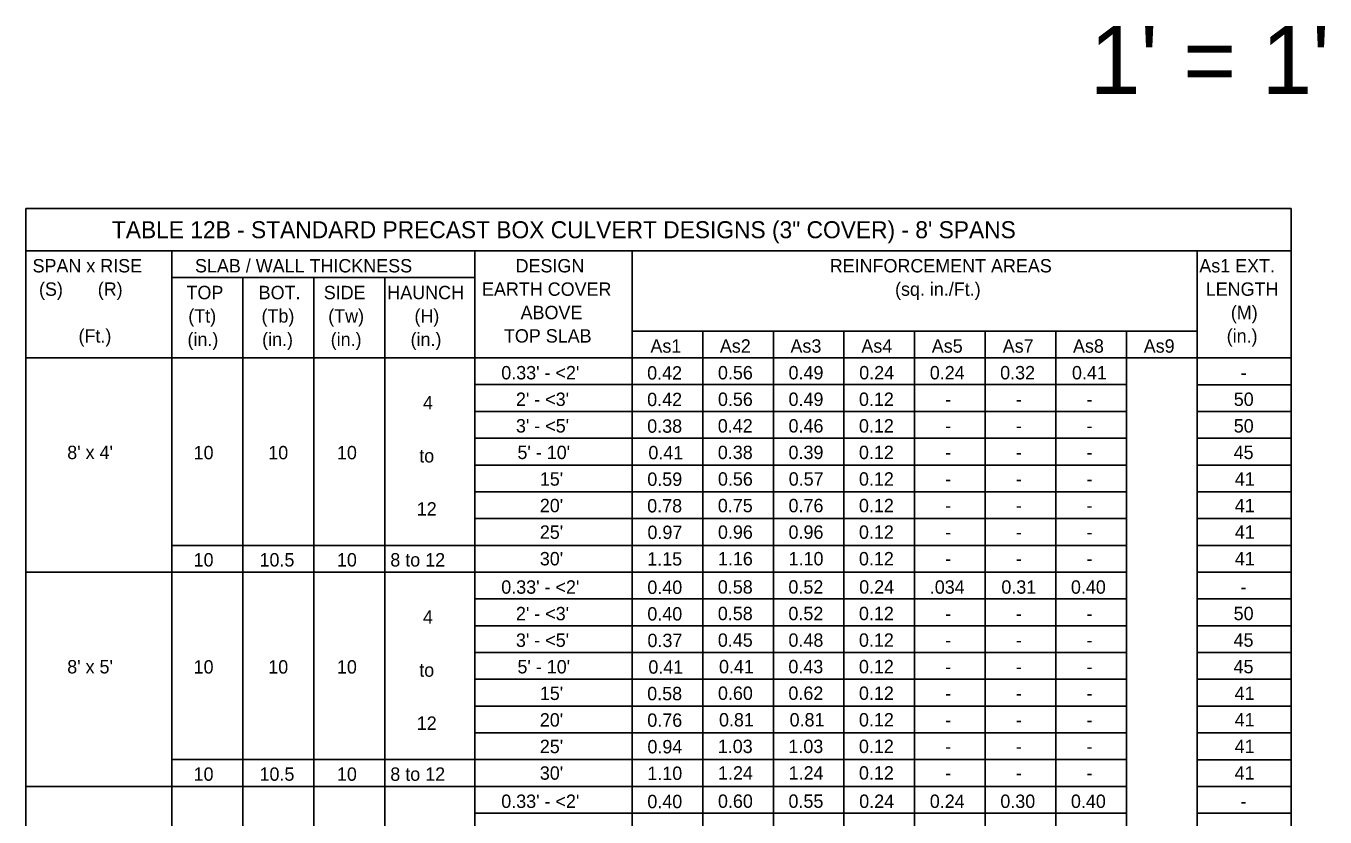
# Model space of a CAD drawing. Extents: x 10342.77 to 10344.98, y 76371.53 to 76372.62.
# Drawn here: x 10343.418 to 10344.028, y 76372.249 to 76372.621 of the extents above; entities that cross this region are included whole.
import ezdxf

# ---------------------------------------------------------------- set-up
doc = ezdxf.new("R2010")
doc.units = 0
doc.layers.add('AdhocPoint_dp', color=7, linetype='Continuous')
doc.layers.add('PlotBorder_dp', color=7, linetype='Continuous')

msp = doc.modelspace()

# ---------------------------------------------------------------- linework, layer by layer
at = {"layer": 'PlotBorder_dp'}
for p, q in [((10343.41763, 76372.53475), (10344.01237, 76372.53475)), ((10343.41763, 76372.53475), (10343.41763, 76371.96053)), ((10344.01237, 76372.53475), (10344.01237, 76371.96053)), ((10343.41763, 76372.51488), (10344.01237, 76372.51488)), ((10343.48627, 76372.51488), (10343.48627, 76371.96053)), ((10343.62871, 76372.51488), (10343.62871, 76371.96053)), ((10343.70259, 76372.51488), (10343.70259, 76371.96053)), ((10343.96818, 76372.51488), (10343.96818, 76371.96053)), ((10343.48627, 76372.50228), (10343.62871, 76372.50228)), ((10343.51963, 76372.50228), (10343.51963, 76371.96053)), ((10343.55299, 76372.50228), (10343.55299, 76371.96053)), ((10343.58635, 76372.50228), (10343.58635, 76371.96053)), ((10343.70259, 76372.47713), (10343.96818, 76372.47713)), ((10343.73579, 76372.47713), (10343.73579, 76371.96053)), ((10343.76899, 76372.47713), (10343.76899, 76371.96053)), ((10343.80219, 76372.47713), (10343.80219, 76371.96053)), ((10343.83539, 76372.47713), (10343.83539, 76371.96053)), ((10343.86858, 76372.47713), (10343.86858, 76371.96053)), ((10343.86858, 76372.47713), (10343.86858, 76371.96053)), ((10343.90178, 76372.47713), (10343.90178, 76371.96053)), ((10343.93498, 76372.47713), (10343.93498, 76371.96053)), ((10343.41763, 76372.46453), (10344.01237, 76372.46453)), ((10343.62871, 76372.45193), (10343.93498, 76372.45193)), ((10343.96818, 76372.45191), (10344.01237, 76372.45191)), ((10343.62871, 76372.43933), (10343.93498, 76372.43933)), ((10343.96818, 76372.43931), (10344.01237, 76372.43931)), ((10343.62871, 76372.42673), (10343.93498, 76372.42673)), ((10343.96818, 76372.42671), (10344.01237, 76372.42671)), ((10343.62871, 76372.41413), (10343.93498, 76372.41413)), ((10343.96818, 76372.41411), (10344.01237, 76372.41411)), ((10343.62871, 76372.40153), (10343.93498, 76372.40153)), ((10343.96818, 76372.40151), (10344.01237, 76372.40151)), ((10343.62871, 76372.38893), (10343.93498, 76372.38893)), ((10343.96818, 76372.38891), (10344.01237, 76372.38891)), ((10343.58635, 76372.37633), (10343.48627, 76372.37633)), ((10343.58635, 76372.37633), (10343.93498, 76372.37633)), ((10343.96818, 76372.37631), (10344.01237, 76372.37631)), ((10343.41763, 76372.36373), (10343.93498, 76372.36373)), ((10343.62334, 76372.36373), (10343.93498, 76372.36373)), ((10343.62931, 76372.36371), (10343.70148, 76372.36371)), ((10343.62931, 76372.36371), (10343.70148, 76372.36371)), ((10343.96818, 76372.36371), (10344.01237, 76372.36371)), ((10343.96818, 76372.36371), (10344.01237, 76372.36371)), ((10343.62871, 76372.35113), (10343.93498, 76372.35113)), ((10343.96818, 76372.35111), (10344.01237, 76372.35111)), ((10343.62871, 76372.33853), (10343.93498, 76372.33853)), ((10343.96818, 76372.33851), (10344.01237, 76372.33851)), ((10343.62871, 76372.32593), (10343.93498, 76372.32593)), ((10343.96818, 76372.32591), (10344.01237, 76372.32591)), ((10343.62871, 76372.31333), (10343.93498, 76372.31333)), ((10343.96818, 76372.31331), (10344.01237, 76372.31331)), ((10343.62871, 76372.30073), (10343.93498, 76372.30073)), ((10343.96818, 76372.30071), (10344.01237, 76372.30071)), ((10343.62871, 76372.28813), (10343.93498, 76372.28813)), ((10343.96818, 76372.28811), (10344.01237, 76372.28811)), ((10343.58635, 76372.27553), (10343.48627, 76372.27553)), ((10343.58635, 76372.27553), (10343.93498, 76372.27553)), ((10343.96818, 76372.27551), (10344.01237, 76372.27551)), ((10343.41763, 76372.26293), (10343.93498, 76372.26293)), ((10343.62334, 76372.26293), (10343.93498, 76372.26293)), ((10343.62931, 76372.26291), (10343.70148, 76372.26291)), ((10343.62931, 76372.26291), (10343.70148, 76372.26291)), ((10343.62931, 76372.26291), (10343.70148, 76372.26291)), ((10343.96818, 76372.26291), (10344.01237, 76372.26291)), ((10343.96818, 76372.26291), (10344.01237, 76372.26291)), ((10343.62871, 76372.25033), (10343.93498, 76372.25033)), ((10343.96818, 76372.25031), (10344.01237, 76372.25031))]:
    msp.add_line(p, q, dxfattribs=at)

# ---------------------------------------------------------------- texts
at = {"layer": 'AdhocPoint_dp'}
for s, height, p in [("1' = 1'", 0.032, (10343.91778, 76372.58867)), ('TABLE 12B - STANDARD PRECAST BOX CULVERT DESIGNS (3" COVER) - 8\' SPANS', 0.008, (10343.45802, 76372.52081)), ('SLAB / WALL THICKNESS', 0.0063, (10343.49709, 76372.50472)), ('As1', 0.0063, (10343.71121, 76372.46696)), ('As2', 0.0063, (10343.74384, 76372.46696)), ('As3', 0.0063, (10343.77704, 76372.46696)), ('As4', 0.0063, (10343.81037, 76372.46696)), ('As5', 0.0063, (10343.84347, 76372.46696)), ('As7', 0.0063, (10343.87681, 76372.46696)), ('As8', 0.0063, (10343.90985, 76372.46696)), ('As9', 0.0063, (10343.9431, 76372.46696)), ('10', 0.0063, (10343.49644, 76372.4168)), ('10', 0.0063, (10343.53153, 76372.4168)), ('10', 0.0063, (10343.56382, 76372.4168)), ('10', 0.0063, (10343.49643, 76372.36638)), ('10.5', 0.0063, (10343.52742, 76372.36638)), ('10', 0.0063, (10343.56381, 76372.36638)), ('8 to 12', 0.0063, (10343.58891, 76372.36638)), ('10', 0.0063, (10343.49644, 76372.31602)), ('10', 0.0063, (10343.53153, 76372.31602)), ('10', 0.0063, (10343.56382, 76372.31602)), ('10', 0.0063, (10343.49643, 76372.26558)), ('10.5', 0.0063, (10343.52742, 76372.26558)), ('10', 0.0063, (10343.56381, 76372.26558)), ('8 to 12', 0.0063, (10343.58891, 76372.26558))]:
    msp.add_text(s, height=height, dxfattribs=at).set_placement(p)
at = {"layer": 'PlotBorder_dp'}
for s, p in [('SPAN x RISE', (10343.42072, 76372.50472)), ('DESIGN', (10343.64781, 76372.50472)), ('REINFORCEMENT AREAS', (10343.79549, 76372.50472)), ('(S)       (R)', (10343.42376, 76372.49372)), ('(sq. in./Ft.)', (10343.82619, 76372.49372)), ('TOP', (10343.49309, 76372.49212)), ('BOT.', (10343.52702, 76372.49212)), ('SIDE', (10343.55762, 76372.49212)), ('HAUNCH', (10343.58751, 76372.49212)), ('EARTH COVER', (10343.63202, 76372.49372)), ('ABOVE', (10343.65016, 76372.48272)), ('(Tt)', (10343.49394, 76372.48112)), ('(Tb)', (10343.52836, 76372.48112)), ('(Tw)', (10343.55972, 76372.48112)), ('(H)', (10343.60025, 76372.48112)), ('(Ft.)', (10343.44234, 76372.47172)), ('(in.)', (10343.49355, 76372.47012)), ('(in.)', (10343.52864, 76372.47012)), ('(in.)', (10343.56088, 76372.47012)), ('(in.)', (10343.59844, 76372.47012)), ('TOP SLAB', (10343.64233, 76372.47172)), ("0.33' - <2'", (10343.64107, 76372.45441)), ('0.42', (10343.70967, 76372.45431)), ('0.56', (10343.74293, 76372.45441)), ('0.49', (10343.77613, 76372.45441)), ('0.24', (10343.80935, 76372.45441)), ('0.24', (10343.84253, 76372.45441)), ('0.32', (10343.87561, 76372.45441)), ('0.41', (10343.90936, 76372.45441)), ('-', (10343.98869, 76372.45441)), ('4', (10343.60429, 76372.44033)), ("2' - <3'", (10343.64797, 76372.44191)), ('0.42', (10343.70967, 76372.44181)), ('0.56', (10343.74293, 76372.44191)), ('0.49', (10343.77613, 76372.44191)), ('0.12', (10343.80922, 76372.44191)), ('50', (10343.98543, 76372.44191)), ('-', (10343.84981, 76372.44191)), ('-', (10343.88302, 76372.44191)), ('-', (10343.9162, 76372.44191)), ("3' - <5'", (10343.64797, 76372.42941)), ('0.38', (10343.70969, 76372.42931)), ('0.42', (10343.74287, 76372.42941)), ('0.46', (10343.77613, 76372.42941)), ('0.12', (10343.80922, 76372.42941)), ('50', (10343.98543, 76372.42941)), ('-', (10343.84981, 76372.42941)), ('-', (10343.88302, 76372.42941)), ('-', (10343.9162, 76372.42941)), ("8' x 4'", (10343.43702, 76372.41691)), ('to', (10343.60251, 76372.41533)), ("5' - 10'", (10343.64868, 76372.41691)), ('0.41', (10343.71024, 76372.41681)), ('0.38', (10343.74288, 76372.41691)), ('0.39', (10343.77613, 76372.41691)), ('0.12', (10343.80922, 76372.41691)), ('45', (10343.98538, 76372.41691)), ('-', (10343.84981, 76372.41691)), ('-', (10343.88302, 76372.41691)), ('-', (10343.9162, 76372.41691)), ("15'", (10343.6592, 76372.40441)), ('0.59', (10343.70973, 76372.40431)), ('0.56', (10343.74293, 76372.40441)), ('0.57', (10343.77621, 76372.40441)), ('0.12', (10343.80922, 76372.40441)), ('41', (10343.98592, 76372.40441)), ('-', (10343.84981, 76372.40441)), ('-', (10343.88302, 76372.40441)), ('-', (10343.9162, 76372.40441)), ('12', (10343.60134, 76372.39033)), ("20'", (10343.6592, 76372.39191)), ('0.78', (10343.70969, 76372.39181)), ('0.75', (10343.74289, 76372.39191)), ('0.76', (10343.77613, 76372.39191)), ('0.12', (10343.80922, 76372.39191)), ('41', (10343.98592, 76372.39191)), ('-', (10343.84981, 76372.39191)), ('-', (10343.88302, 76372.39191)), ('-', (10343.9162, 76372.39191)), ("25'", (10343.6592, 76372.37941)), ('0.97', (10343.70981, 76372.37931)), ('0.96', (10343.74293, 76372.37941)), ('0.96', (10343.77613, 76372.37941)), ('0.12', (10343.80922, 76372.37941)), ('41', (10343.98592, 76372.37941)), ('-', (10343.84981, 76372.37941)), ('-', (10343.88302, 76372.37941)), ('-', (10343.9162, 76372.37941)), ("30'", (10343.6592, 76372.36691)), ('1.15', (10343.70969, 76372.36681)), ('1.16', (10343.74293, 76372.36691)), ('1.10', (10343.77615, 76372.36691)), ('0.12', (10343.80922, 76372.36691)), ('41', (10343.98592, 76372.36691)), ('-', (10343.84981, 76372.36691)), ('-', (10343.88302, 76372.36691)), ('-', (10343.9162, 76372.36691)), ("0.33' - <2'", (10343.64107, 76372.35358)), ('0.40', (10343.70975, 76372.35347)), ('0.58', (10343.74288, 76372.35363)), ('0.52', (10343.77607, 76372.35363)), ('0.24', (10343.80935, 76372.35363)), ('.034', (10343.84253, 76372.35358)), ('0.31', (10343.87618, 76372.35358)), ('0.40', (10343.90888, 76372.35358)), ('-', (10343.98864, 76372.35363)), ('4', (10343.60429, 76372.33953)), ("2' - <3'", (10343.64797, 76372.34108)), ('0.40', (10343.70975, 76372.34097)), ('0.58', (10343.74288, 76372.34113)), ('0.52', (10343.77607, 76372.34113)), ('0.12', (10343.80922, 76372.34113)), ('-', (10343.84981, 76372.34108)), ('-', (10343.88302, 76372.34108)), ('-', (10343.9162, 76372.34108)), ('50', (10343.98538, 76372.34113)), ("3' - <5'", (10343.64797, 76372.32858)), ('0.37', (10343.70981, 76372.32847)), ('0.45', (10343.74289, 76372.32863)), ('0.48', (10343.77609, 76372.32863)), ('0.12', (10343.80922, 76372.32863)), ('-', (10343.84981, 76372.32858)), ('-', (10343.88302, 76372.32858)), ('-', (10343.9162, 76372.32858)), ('45', (10343.98533, 76372.32863)), ("8' x 5'", (10343.43702, 76372.31608)), ('to', (10343.60251, 76372.31453)), ("5' - 10'", (10343.64868, 76372.31608)), ('0.41', (10343.71024, 76372.31597)), ('0.41', (10343.74343, 76372.31613)), ('0.43', (10343.77606, 76372.31613)), ('0.12', (10343.80922, 76372.31613)), ('-', (10343.84981, 76372.31608)), ('-', (10343.88302, 76372.31608)), ('-', (10343.9162, 76372.31608)), ('45', (10343.98533, 76372.31613)), ("15'", (10343.6592, 76372.30358)), ('0.58', (10343.70969, 76372.30347)), ('0.60', (10343.74294, 76372.30363)), ('0.62', (10343.77607, 76372.30363)), ('0.12', (10343.80922, 76372.30363)), ('-', (10343.84981, 76372.30358)), ('-', (10343.88302, 76372.30358)), ('-', (10343.9162, 76372.30358)), ('41', (10343.98587, 76372.30363)), ('12', (10343.60134, 76372.28953)), ("20'", (10343.6592, 76372.29108)), ('0.76', (10343.70973, 76372.29097)), ('0.81', (10343.74343, 76372.29113)), ('0.81', (10343.77663, 76372.29113)), ('0.12', (10343.80922, 76372.29113)), ('-', (10343.84981, 76372.29108)), ('-', (10343.88302, 76372.29108)), ('-', (10343.9162, 76372.29108)), ('41', (10343.98587, 76372.29113)), ("25'", (10343.6592, 76372.27858)), ('0.94', (10343.70979, 76372.27847)), ('1.03', (10343.74286, 76372.27863)), ('1.03', (10343.77606, 76372.27863)), ('0.12', (10343.80922, 76372.27863)), ('-', (10343.84981, 76372.27858)), ('-', (10343.88302, 76372.27858)), ('-', (10343.9162, 76372.27858)), ('41', (10343.98587, 76372.27863)), ("30'", (10343.6592, 76372.26608)), ('1.10', (10343.70975, 76372.26597)), ('1.24', (10343.74299, 76372.26613)), ('1.24', (10343.77619, 76372.26613)), ('0.12', (10343.80922, 76372.26613)), ('-', (10343.84981, 76372.26608)), ('-', (10343.88302, 76372.26608)), ('-', (10343.9162, 76372.26608)), ('41', (10343.98587, 76372.26613)), ("0.33' - <2'", (10343.64107, 76372.2528)), ('0.40', (10343.70975, 76372.25269)), ('0.60', (10343.74294, 76372.25285)), ('0.55', (10343.77609, 76372.25285)), ('0.24', (10343.80935, 76372.2528)), ('0.24', (10343.84253, 76372.2528)), ('0.30', (10343.87569, 76372.2528)), ('0.40', (10343.90888, 76372.2528)), ('-', (10343.98864, 76372.2528))]:
    msp.add_text(s, height=0.0063, dxfattribs=at).set_placement(p)
for s, p in [('As1 EXT.', (10343.96923, 76372.50472)), ('LENGTH', (10343.97225, 76372.49372)), ('(M)', (10343.98406, 76372.48272)), ('(in.)', (10343.9821, 76372.47172))]:
    msp.add_text(s, height=0.0063, rotation=360, dxfattribs=at).set_placement(p)

doc.saveas('drawing.dxf')
